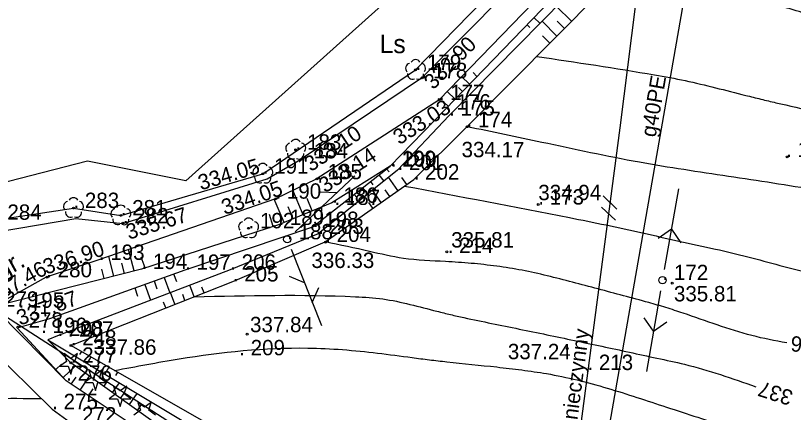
# Model space of a CAD drawing. Extents: x 4632591 to 4653165, y 5351032 to 5369868.
# Drawn here: x 4644617.6 to 4644693.5, y 5358423.6 to 5358462.3 of the extents above; entities that cross this region are included whole.
import ezdxf

# ---------------------------------------------------------------- set-up
doc = ezdxf.new("R2010")
doc.units = 0
for name, color, linetype in [('EDZPX_299', 7, 'Continuous'), ('EKLPK_217', 7, 'Continuous'), ('EUZPU_424', 7, 'Continuous'), ('SZZPZ_921', 7, 'Continuous'), ('SZZPZ_922', 7, 'Continuous'), ('SZZTZ_925', 7, 'Continuous'), ('UEEPA_510', 7, 'Continuous'), ('UEEPO_585', 7, 'Continuous'), ('UEETA_516', 7, 'Continuous'), ('UGGPO_553', 7, 'Continuous'), ('UTTTA_521', 7, 'Continuous'), ('Warstwa 40', 7, 'Continuous'), ('Warstwa 62', 7, 'Continuous'), ('WUKPS_403', 7, 'Continuous'), ('WUKPS_820', 7, 'Continuous'), ('WUKPS_823', 7, 'Continuous'), ('WUKPS_824', 7, 'Continuous'), ('WWRPH_811', 7, 'Continuous')]:
    doc.layers.add(name, color=color, linetype=linetype)

msp = doc.modelspace()

# ---------------------------------------------------------------- linework, layer by layer
at = {"layer": 'EDZPX_299'}
for p, q in [((4644676.32, 5358443.397), (4644674.977, 5358444.684)), ((4644676.176, 5358442.307), (4644674.833, 5358443.594))]:
    msp.add_line(p, q, dxfattribs=at)
at = {"layer": 'EKLPK_217'}
msp.add_lwpolyline([(4644589.438, 5358446.057), (4644590.15, 5358443.3), (4644594.36, 5358439.41), (4644607.9, 5358437.69), (4644615.73, 5358442.35), (4644623.29, 5358443.5), (4644627.91, 5358442.78), (4644641.76, 5358446.85), (4644656.67, 5358456.98), (4644668.51, 5358469.17), (4644674.28, 5358475.79), (4644680.615, 5358483.058), (4644678.245, 5358495.411), (4644671.513, 5358518.446)], dxfattribs=at)
at = {"layer": 'EUZPU_424'}
msp.add_line((4644615.41, 5358433.87), (4644622.58, 5358426.64), dxfattribs=at)
for points in [[(4644736.52, 5358573.425), (4644734.734, 5358569.58), (4644733.014, 5358558.487), (4644724.43, 5358530.37), (4644718.67, 5358515.99), (4644711.55, 5358501.11), (4644708.07, 5358496.17), (4644703.46, 5358490.97), (4644685.13, 5358478.64), (4644676.84, 5358472.22), (4644671.23, 5358466.74), (4644658.94, 5358454.03), (4644646.98, 5358446.31), (4644643, 5358444.41)], [(4644729.51, 5358555.12), (4644722.11, 5358531.42), (4644716.49, 5358516.97), (4644709.43, 5358502.48), (4644706.31, 5358497.61), (4644701.62, 5358493.26), (4644695.208, 5358490.354), (4644683.44, 5358482.53), (4644675.12, 5358474.36), (4644669.43, 5358468.46), (4644657.26, 5358456.17), (4644645.62, 5358448.34)], [(4644588.182, 5358440.711), (4644594.11, 5358438.64), (4644607.85, 5358435.87), (4644616.001, 5358441.219), (4644623.539, 5358442.477), (4644628.11, 5358442), (4644642.179, 5358446.335), (4644645.62, 5358448.34)], [(4644643, 5358444.41), (4644625.77, 5358438.44), (4644620.64, 5358436.74), (4644615.41, 5358433.87)], [(4644612.98, 5358431.93), (4644621.22, 5358423.87), (4644623.01, 5358422.57)], [(4644675.121, 5358297.602), (4644676.248, 5358300.881), (4644677.005, 5358304.092), (4644679.073, 5358313.341), (4644680.722, 5358320.714), (4644680.919, 5358321.592), (4644681.429, 5358324.885), (4644682.537, 5358331.059), (4644684.504, 5358343.896), (4644686.022, 5358352.777), (4644686.732, 5358361.758), (4644688.28, 5358374.66), (4644687.59, 5358381.7), (4644684.88, 5358385.07), (4644678.84, 5358389.1), (4644673.9, 5358392.63), (4644663.63, 5358399.66), (4644641.5, 5358414), (4644622.58, 5358426.64)]]:
    msp.add_lwpolyline(points, dxfattribs=at)
at = {"layer": 'SZZPZ_921'}
for p, q in [((4644623.03, 5358428.822), (4644622.38, 5358429.294)), ((4644622.38, 5358429.294), (4644622.628, 5358428.53)), ((4644623.68, 5358429.294), (4644623.03, 5358428.822)), ((4644623.431, 5358428.529), (4644623.68, 5358429.294)), ((4644622.628, 5358428.53), (4644621.979, 5358428.058)), ((4644624.081, 5358428.058), (4644623.431, 5358428.529)), ((4644621.979, 5358428.058), (4644622.781, 5358428.058)), ((4644622.781, 5358428.058), (4644623.03, 5358427.294)), ((4644623.03, 5358427.294), (4644623.278, 5358428.058)), ((4644623.278, 5358428.058), (4644624.081, 5358428.058))]:
    msp.add_line(p, q, dxfattribs=at)
msp.add_circle((4644623.03, 5358428.4), 0.09, dxfattribs=at)
at = {"layer": 'SZZPZ_922'}
for centre in [(4644656.67, 5358456.98), (4644644.97, 5358449.19), (4644641.76, 5358446.85), (4644623.29, 5358443.5), (4644627.91, 5358442.78), (4644640.38, 5358441.52)]:
    msp.add_circle(centre, 0.09, dxfattribs=at)
for centre, start, end in [((4644656.677, 5358457.48), 30.76957, 149.23063), ((4644656.201, 5358457.132), 103.05194, 221.33515), ((4644657.152, 5358457.137), 318.93901, 77.55513), ((4644656.378, 5358456.579), 174.17267, 292.61566), ((4644656.966, 5358456.572), 246.13103, 4.5225), ((4644644.501, 5358449.342), 103.05194, 221.33515), ((4644644.977, 5358449.69), 30.76957, 149.23063), ((4644645.452, 5358449.347), 318.93901, 77.55513), ((4644644.678, 5358448.789), 174.17267, 292.61566), ((4644645.266, 5358448.782), 246.13103, 4.5225), ((4644641.291, 5358447.002), 103.05194, 221.33515), ((4644641.767, 5358447.35), 30.76957, 149.23063), ((4644642.242, 5358447.007), 318.93901, 77.55513), ((4644641.468, 5358446.449), 174.17267, 292.61566), ((4644642.056, 5358446.442), 246.13103, 4.5225), ((4644623.297, 5358444), 30.76957, 149.23063), ((4644622.821, 5358443.652), 103.05194, 221.33515), ((4644623.772, 5358443.657), 318.93901, 77.55513), ((4644627.917, 5358443.28), 30.76957, 149.23063), ((4644622.998, 5358443.099), 174.17267, 292.61566), ((4644623.586, 5358443.092), 246.13103, 4.5225), ((4644627.441, 5358442.932), 103.05194, 221.33515), ((4644628.392, 5358442.937), 318.93901, 77.55513), ((4644627.618, 5358442.379), 174.17267, 292.61566), ((4644628.206, 5358442.372), 246.13103, 4.5225), ((4644639.911, 5358441.672), 103.05194, 221.33515), ((4644640.387, 5358442.02), 30.76957, 149.23063), ((4644640.862, 5358441.677), 318.93901, 77.55513), ((4644640.088, 5358441.119), 174.17267, 292.61566), ((4644640.676, 5358441.112), 246.13103, 4.5225)]:
    msp.add_arc(centre, 0.5, start, end, dxfattribs=at)
at = {"layer": 'SZZTZ_925'}
for p, q in [((4644625.432, 5358427.235), (4644624.782, 5358427.707)), ((4644624.782, 5358427.707), (4644625.03, 5358426.943)), ((4644626.082, 5358427.707), (4644625.432, 5358427.235)), ((4644625.833, 5358426.942), (4644626.082, 5358427.707)), ((4644625.03, 5358426.943), (4644624.381, 5358426.471)), ((4644626.483, 5358426.471), (4644625.833, 5358426.942)), ((4644624.381, 5358426.471), (4644625.183, 5358426.471)), ((4644625.183, 5358426.471), (4644625.432, 5358425.707)), ((4644625.432, 5358425.707), (4644625.68, 5358426.471)), ((4644625.68, 5358426.471), (4644626.483, 5358426.471)), ((4644627.835, 5358425.648), (4644627.185, 5358426.12)), ((4644627.185, 5358426.12), (4644627.433, 5358425.356)), ((4644628.485, 5358426.12), (4644627.835, 5358425.648)), ((4644628.236, 5358425.355), (4644628.485, 5358426.12)), ((4644627.433, 5358425.356), (4644626.784, 5358424.884)), ((4644628.886, 5358424.884), (4644628.236, 5358425.355)), ((4644626.784, 5358424.884), (4644627.586, 5358424.884)), ((4644627.586, 5358424.884), (4644627.835, 5358424.12)), ((4644627.835, 5358424.12), (4644628.083, 5358424.884)), ((4644628.083, 5358424.884), (4644628.886, 5358424.884)), ((4644630.237, 5358424.061), (4644629.587, 5358424.533)), ((4644629.587, 5358424.533), (4644629.835, 5358423.769)), ((4644630.887, 5358424.533), (4644630.237, 5358424.061)), ((4644630.638, 5358423.768), (4644630.887, 5358424.533)), ((4644629.835, 5358423.769), (4644629.186, 5358423.297)), ((4644631.288, 5358423.297), (4644630.638, 5358423.768))]:
    msp.add_line(p, q, dxfattribs=at)
at = {"layer": 'UEEPA_510'}
for centre in [(4644644.15, 5358440.45), (4644680.77, 5358436.46)]:
    msp.add_circle(centre, 0.35, dxfattribs=at)
at = {"layer": 'UEEPO_585'}
msp.add_lwpolyline([(4644654.756, 5358408.317), (4644637.887, 5358419.204), (4644615.627, 5358433.571), (4644614.206, 5358434.487), (4644594.947, 5358438.482), (4644591.953, 5358439.845), (4644585.885, 5358446.338)], dxfattribs=at)
at = {"layer": 'UEETA_516'}
for p, q in [((4644680.955, 5358437.494), (4644682.361, 5358445.369)), ((4644681.658, 5358441.431), (4644680.346, 5358440.517)), ((4644681.658, 5358441.431), (4644682.572, 5358440.119)), ((4644680.588, 5358435.426), (4644679.199, 5358427.547)), ((4644679.894, 5358431.487), (4644678.976, 5358432.797)), ((4644679.894, 5358431.487), (4644681.204, 5358432.404))]:
    msp.add_line(p, q, dxfattribs=at)
at = {"layer": 'UGGPO_553'}
for points in [[(4644681.163, 5358527.28), (4644681.159, 5358525.743), (4644681.15, 5358522.056), (4644680.113, 5358495.078), (4644679.631, 5358475.318), (4644676.612, 5358451.335), (4644670.677, 5358406.387), (4644669.873, 5358402.059), (4644670.021, 5358384.82), (4644670.096, 5358376.26)], [(4644705.94, 5358488.66), (4644690.958, 5358475.612), (4644684.277, 5358472.067), (4644671.393, 5358398.424), (4644670.038, 5358391.221), (4644669.59, 5358385.606), (4644670.719, 5358377.845), (4644670.409, 5358376.132)]]:
    msp.add_lwpolyline(points, dxfattribs=at)
at = {"layer": 'UTTTA_521'}
for p, q in [((4644644.917, 5358441.167), (4644650.759, 5358446.633)), ((4644649.006, 5358444.993), (4644647.408, 5358445.046)), ((4644647.495, 5358443.58), (4644647.442, 5358441.981)), ((4644644.537, 5358439.474), (4644647.482, 5358432.036)), ((4644645.837, 5358436.191), (4644644.369, 5358436.826)), ((4644646.599, 5358434.267), (4644647.234, 5358435.735))]:
    msp.add_line(p, q, dxfattribs=at)
at = {"layer": 'Warstwa 40'}
msp.add_lwpolyline([(4644810.83, 5358555.032), (4644734.325, 5358627.586), (4644688.904, 5358576.341), (4644696.209, 5358541.054), (4644665.65, 5358513.079), (4644675.21, 5358482.875), (4644634.264, 5358446.155), (4644624.66, 5358448.078), (4644610.341, 5358444.406), (4644593.083, 5358445.769), (4644584.821, 5358446.422), (4644558.95, 5358331.355), (4644690.288, 5358293.195), (4644705.733, 5358386.519), (4644692.287, 5358404.572), (4644776.59, 5358522.672)], close=True, dxfattribs=at)
at = {"layer": 'WUKPS_403'}
for centre in [(4644657.312, 5358456.211), (4644658.988, 5358454.094), (4644661.713, 5358451.433), (4644645.7, 5358448.379), (4644692.929, 5358448.484), (4644641.76, 5358446.85), (4644647.028, 5358446.339), (4644643.053, 5358444.41), (4644668.65, 5358443.84), (4644628.118, 5358442.033), (4644647.878, 5358440.172), (4644659.726, 5358439.221), (4644620.718, 5358436.751), (4644681.726, 5358436.162), (4644617.847, 5358431.874), (4644640.239, 5358431.194), (4644623.05, 5358430.088), (4644671.473, 5358429.793)]:
    msp.add_circle(centre, 0.09, dxfattribs=at)
at = {"layer": 'WUKPS_820'}
for p, q in [((4644671.893, 5358461.721), (4644670.434, 5358463.167)), ((4644668.219, 5358462.102), (4644668.817, 5358461.525)), ((4644670.467, 5358460.283), (4644669.013, 5358461.724)), ((4644671.206, 5358461.029), (4644670.478, 5358461.751)), ((4644667.544, 5358461.402), (4644667.839, 5358461.117)), ((4644669.781, 5358459.591), (4644669.055, 5358460.31)), ((4644662.665, 5358456.341), (4644662.279, 5358456.712)), ((4644661.938, 5358455.587), (4644661.165, 5358456.331)), ((4644660.536, 5358454.133), (4644659.762, 5358454.88)), ((4644661.263, 5358454.887), (4644660.876, 5358455.26)), ((4644659.862, 5358453.433), (4644659.474, 5358453.807)), ((4644653.849, 5358447.323), (4644654.084, 5358447.024)), ((4644653.088, 5358446.724), (4644653.565, 5358446.119)), ((4644652.269, 5358446.078), (4644652.51, 5358445.771)), ((4644654.96, 5358445.2), (4644654.041, 5358446.502)), ((4644655.817, 5358445.805), (4644655.338, 5358446.483)), ((4644645.699, 5358442.845), (4644644.714, 5358445.228)), ((4644651.508, 5358445.478), (4644651.996, 5358444.858)), ((4644653.307, 5358444.034), (4644652.462, 5358445.232)), ((4644654.164, 5358444.639), (4644653.722, 5358445.265)), ((4644643.841, 5358442.077), (4644642.892, 5358444.373)), ((4644646.593, 5358443.214), (4644646.091, 5358444.43)), ((4644650.689, 5358444.833), (4644650.936, 5358444.518)), ((4644644.735, 5358442.447), (4644644.254, 5358443.613)), ((4644652.512, 5358443.473), (4644652.106, 5358444.047)), ((4644642.793, 5358441.69), (4644642.408, 5358442.881)), ((4644629.204, 5358437.357), (4644628.676, 5358439.446)), ((4644627.244, 5358436.861), (4644626.758, 5358438.782)), ((4644630.278, 5358437.673), (4644629.887, 5358438.701)), ((4644626.3, 5358436.623), (4644626.067, 5358437.542)), ((4644628.26, 5358437.118), (4644628.006, 5358438.122)), ((4644632.151, 5358436.736), (4644632.697, 5358435.22)), ((4644633.065, 5358437.065), (4644633.335, 5358436.316)), ((4644630.253, 5358436.052), (4644630.813, 5358434.497)), ((4644631.167, 5358436.381), (4644631.444, 5358435.613)), ((4644635.079, 5358434.846), (4644634.637, 5358435.965)), ((4644629.269, 5358435.697), (4644629.552, 5358434.909)), ((4644633.199, 5358434.103), (4644632.75, 5358435.241)), ((4644636.054, 5358435.231), (4644635.835, 5358435.786)), ((4644634.174, 5358434.488), (4644633.951, 5358435.052)), ((4644632.293, 5358433.746), (4644632.067, 5358434.319)), ((4644624.071, 5358429.495), (4644623.897, 5358429.191)), ((4644624.981, 5358428.974), (4644624.622, 5358428.346)), ((4644625.827, 5358428.491), (4644625.641, 5358428.167)), ((4644621.563, 5358427.742), (4644622.116, 5358428.252)), ((4644622.275, 5358426.971), (4644623.471, 5358428.075)), ((4644626.737, 5358427.97), (4644626.355, 5358427.301)), ((4644623.078, 5358426.308), (4644623.541, 5358427.001)), ((4644623.949, 5358425.725), (4644624.858, 5358427.086)), ((4644627.583, 5358427.487), (4644627.386, 5358427.142)), ((4644626.252, 5358426.096), (4644626.569, 5358426.539)), ((4644627.104, 5358425.487), (4644627.784, 5358426.439)), ((4644624.758, 5358425.185), (4644625.204, 5358425.853)), ((4644627.894, 5358424.922), (4644628.256, 5358425.429)), ((4644628.745, 5358424.314), (4644629.518, 5358425.394)), ((4644629.535, 5358423.749), (4644629.944, 5358424.32))]:
    msp.add_line(p, q, dxfattribs=at)
at = {"layer": 'WUKPS_823'}
for points in [[(4644677.51, 5358471.74), (4644659.55, 5358453.11), (4644654.2, 5358447.6), (4644648.52, 5358444.01), (4644643.29, 5358441.85), (4644629.93, 5358437.54), (4644615.41, 5358433.87)], [(4644639.94, 5358420.42), (4644623.03, 5358430.09), (4644638.84, 5358436.33), (4644647.86, 5358440.19), (4644656.49, 5358446.28), (4644661.65, 5358451.39), (4644679.02, 5358468.91)], [(4644617.8, 5358431.82), (4644620.972, 5358432.708), (4644634.19, 5358437.47), (4644646.65, 5358441.65), (4644654.2, 5358447.6)], [(4644617.8, 5358431.82), (4644622.58, 5358426.64)]]:
    msp.add_lwpolyline(points, dxfattribs=at)
at = {"layer": 'WUKPS_824'}
for points in [[(4644677.95, 5358470.8), (4644659.95, 5358452.52), (4644654.91, 5358447.2), (4644647.16, 5358440.97), (4644638.59, 5358437.48), (4644621.75, 5358431.02), (4644620.787, 5358430.651)], [(4644666.89, 5358400.78), (4644664.19, 5358400.86), (4644640.54, 5358415.88), (4644623.03, 5358428.4), (4644620.787, 5358430.651)], [(4644620.787, 5358430.651), (4644639.361, 5358419.468), (4644656.41, 5358407.65), (4644666.437, 5358400.793)]]:
    msp.add_lwpolyline(points, dxfattribs=at)
at = {"layer": 'WWRPH_811'}
for points in [[(4644710.618, 5358459.182), (4644707.835, 5358459.559), (4644705.06, 5358460.015), (4644702.293, 5358460.533), (4644699.534, 5358461.099), (4644697.222, 5358461.691), (4644694.942, 5358462.396), (4644692.662, 5358463.094), (4644690.352, 5358463.666), (4644688.455, 5358464.042), (4644686.556, 5358464.404), (4644682.744, 5358465.042), (4644676.147, 5358466.012)], [(4644668.499, 5358458.298), (4644679.999, 5358456.496), (4644682.981, 5358455.934), (4644685.939, 5358455.241), (4644688.886, 5358454.497), (4644690.361, 5358454.13), (4644691.839, 5358453.78), (4644695.709, 5358452.895), (4644699.585, 5358452.021), (4644701.591, 5358451.661), (4644703.618, 5358451.436), (4644705.657, 5358451.306), (4644707.698, 5358451.228)], [(4644703.415, 5358443.858), (4644701.532, 5358444.177), (4644699.651, 5358444.535), (4644697.771, 5358444.896), (4644695.89, 5358445.222), (4644687.2, 5358446.59), (4644678.511, 5358447.965), (4644668.987, 5358449.909), (4644661.703, 5358451.433)], [(4644655.59, 5358445.645), (4644671.686, 5358442.57), (4644675.258, 5358441.847), (4644678.819, 5358441.071), (4644682.377, 5358440.276), (4644685.938, 5358439.495), (4644689.082, 5358438.742), (4644692.221, 5358437.906), (4644695.364, 5358437.103), (4644698.522, 5358436.447)], [(4644692.887, 5358430.339), (4644689.473, 5358431.051), (4644686.116, 5358432.09), (4644682.779, 5358433.237), (4644681.105, 5358433.783), (4644679.421, 5358434.274), (4644674.477, 5358435.599), (4644669.514, 5358436.885), (4644667.065, 5358437.422), (4644664.593, 5358437.821), (4644662.104, 5358438.1), (4644659.607, 5358438.277), (4644655.481, 5358438.586), (4644652.17, 5358439.268), (4644647.86, 5358440.19)], [(4644635.073, 5358434.843), (4644650.799, 5358434.843), (4644653.477, 5358434.627), (4644656.126, 5358434.097), (4644658.762, 5358433.43), (4644660.08, 5358433.102), (4644661.4, 5358432.806), (4644666.787, 5358431.694), (4644672.168, 5358430.571), (4644677.543, 5358429.427), (4644680.228, 5358428.844), (4644682.912, 5358428.252), (4644689.876, 5358426.057)], [(4644627.307, 5358427.644), (4644633.608, 5358428.776), (4644646.157, 5358429.837), (4644652.95, 5358429.346), (4644656.337, 5358428.906), (4644658.031, 5358428.689), (4644659.726, 5358428.492), (4644664.602, 5358427.986), (4644667.035, 5358427.695), (4644668.25, 5358427.526), (4644669.463, 5358427.336), (4644672.439, 5358426.722), (4644675.371, 5358425.926), (4644678.274, 5358425.019), (4644681.163, 5358424.071), (4644687.248, 5358422.076), (4644687.736, 5358421.913)], [(4644620.197, 5358424.87), (4644615.364, 5358424.87), (4644610.196, 5358424.531)]]:
    msp.add_spline(points, degree=3, dxfattribs=at)

# ---------------------------------------------------------------- texts
at = {"layer": 'EKLPK_217'}
msp.add_text('Ls', height=1.8, dxfattribs=at).set_placement((4644653.169, 5358458.615))
at = {"layer": 'EUZPU_424'}
msp.add_text('dr.gr.', height=1.8, rotation=28.75609, dxfattribs=at).set_placement((4644613.804, 5358435.178))
at = {"layer": 'UGGPO_553'}
for s, rotation, p in [('g40PE', 80.07565, (4644680.098, 5358450.352)), ('gA65 nieczynny', 82.47691, (4644671.776, 5358417.575))]:
    msp.add_text(s, height=1.5, rotation=rotation, dxfattribs=at).set_placement(p)
at = {"layer": 'Warstwa 62'}
for s, p in [('. 179', (4644656.67, 5358456.98)), ('. 178', (4644657.26, 5358456.17)), ('. 177', (4644658.94, 5358454.03)), ('. 176', (4644659.55, 5358453.11)), ('. 175', (4644659.95, 5358452.52)), ('. 174', (4644661.65, 5358451.39)), ('. 183', (4644644.97, 5358449.19)), ('. 184', (4644645.62, 5358448.34)), ('. 169', (4644692.83, 5358448.49)), ('. 199', (4644654.2, 5358447.6)), ('. 200', (4644654.26, 5358447.53)), ('. 191', (4644641.76, 5358446.85)), ('. 201', (4644654.91, 5358447.2)), ('. 185', (4644646.98, 5358446.31)), ('. 202', (4644656.49, 5358446.28)), ('. 190', (4644643, 5358444.41)), ('. 283', (4644623.29, 5358443.5)), ('. 186', (4644648.52, 5358444.01)), ('. 187', (4644648.76, 5358443.8)), ('. 173', (4644668.65, 5358443.84)), ('. 281', (4644627.91, 5358442.78)), ('. 284', (4644615.73, 5358442.35)), ('. 282', (4644628.11, 5358442)), ('. 192', (4644640.38, 5358441.52)), ('. 189', (4644643.29, 5358441.85)), ('. 198', (4644646.65, 5358441.65)), ('. 188', (4644644.15, 5358440.45)), ('. 203', (4644647.16, 5358440.97)), ('. 204', (4644647.86, 5358440.19)), ('. 214', (4644659.81, 5358439.12)), ('. 193', (4644625.77, 5358438.44)), ('. 194', (4644629.93, 5358437.54)), ('. 197', (4644634.19, 5358437.47)), ('. 206', (4644638.59, 5358437.48)), ('. 280', (4644620.64, 5358436.74)), ('. 205', (4644638.84, 5358436.33)), ('. 172', (4644680.77, 5358436.46)), ('. 279', (4644615.41, 5358433.87)), ('. 195', (4644617.93, 5358433.76)), ('. 278', (4644617.8, 5358431.82)), ('. 196', (4644620.14, 5358431.3)), ('. 208', (4644621.75, 5358431.02)), ('. 207', (4644622.73, 5358430.93)), ('. 248', (4644623.03, 5358430.09)), ('. 209', (4644639.47, 5358429.13)), ('. 277', (4644623.03, 5358428.4)), ('. 213', (4644673.44, 5358427.69)), ('. 276', (4644622.58, 5358426.64)), ('. 275', (4644621.22, 5358423.87)), ('. 272', (4644623.01, 5358422.57))]:
    msp.add_text(s, height=1.5, dxfattribs=at).set_placement(p)
at = {"layer": 'WUKPS_403'}
for s, rotation, p in [('332.90', 45.28109, (4644658.405, 5358454.979)), ('333.03', 32.84163, (4644655.097, 5358449.615)), ('333.10', 33.92795, (4644646.467, 5358446.99)), ('333.14', 32.84163, (4644647.853, 5358444.925)), ('334.05', 16.3761, (4644635.713, 5358445.218)), ('334.05', 19.11062, (4644638.041, 5358442.814)), ('335.67', 17.12642, (4644628.692, 5358440.398)), ('336.90', 18.33437, (4644620.618, 5358436.992)), ('337.46', 28.75609, (4644615.469, 5358434.154)), ('337.87', 19.8124, (4644618.067, 5358432.014))]:
    msp.add_text(s, height=1.5, rotation=rotation, dxfattribs=at).set_placement(p)
for s, p in [('334.17', (4644661.163, 5358448.459)), ('334.94', (4644668.65, 5358444.267)), ('335.81', (4644660.148, 5358439.647)), ('336.33', (4644646.51, 5358437.647)), ('335.81', (4644681.885, 5358434.389)), ('337.84', (4644640.522, 5358431.381)), ('337.86', (4644625.256, 5358429.183)), ('337.24', (4644665.679, 5358428.746))]:
    msp.add_text(s, height=1.5, dxfattribs=at).set_placement(p)
at = {"layer": 'WWRPH_811'}
for s, rotation, p in [('336', 175.30548, (4644696.686, 5358430.748)), ('337', 162.37193, (4644693.615, 5358425.615))]:
    msp.add_text(s, height=1.5, rotation=rotation, dxfattribs=at).set_placement(p)

doc.saveas('drawing.dxf')
